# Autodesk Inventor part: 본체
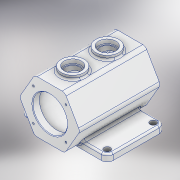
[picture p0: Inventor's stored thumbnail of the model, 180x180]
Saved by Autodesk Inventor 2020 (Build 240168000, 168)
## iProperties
Created: 2021-06
Part Number: 본체
Material: 알루미늄 6061
Document SubType Name: Modeling
Designer: 605-5
Mass: 1495.74 g
Surface Area: 1102.12 cm^2
Volume: 553.978 cm^3
Density: 2.7 g/cm^3
Appearance: 알루미늄 - 평지
Author: 605-5
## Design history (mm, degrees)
sketch "스케치1" dims "d0" = 105
  geometry: L1 (-26.25, 45.466)-(26.25, 45.466); L2 (26.25, 45.466)-(52.5, 0); L3 (52.5, 0)-(26.25, -45.466); L4 (26.25, -45.466)-(-26.25, -45.466); L5 (-26.25, -45.466)-(-52.5, 0); L6 (-52.5, 0)-(-26.25, 45.466); 3 further points
  constraints: 12 end point, 2 coincident, 1 horizontal alignment, 16 other
extrude "돌출1" new body sketch "스케치1" stored distance "d1" = 140; taper "d2" = 0 deg
node "작업 평면1"
sketch "스케치5"
  geometry: L1 (-75, -55)-(75, -55); L2 (75, -55)-(75, 45); L3 (75, 45)-(-75, 45); L4 (-75, 45)-(-75, -55); L5 (52.5, -70)-(26.25, -70) reference; L6 (26.25, 70)-(52.5, 70) reference; 3 further points
  constraints: 8 end point, 2 midpoint, 2 parallel, 1 horizontal, 1 perpendicular, 1 vertical alignment
  dimensions: "d27" = 150 distance between parallel lines of L2 L4; "d28" = 100 distance between parallel lines of L3 L1; "d103" = 25 distance between parallel lines of L3 L6
extrude "돌출4" join sketch "스케치5" distance "d29" = 12; taper "d30" = 0 deg
node "작업 평면2"
sketch "스케치6"
  geometry: L1 (-26.25, 70)-(26.25, 70) reference; C1 r 20 at (0, 30); C2 r 20 at (0, -30); 1 further point
  constraints: 2 centre point, 2 vertical alignment, 1 equal radius
  dimensions: "d32" = 40 diameter of C2; "d33" = 60 distance of C2.centre C1.centre; "d34" = 40 distance from line of C1.centre L1
extrude "돌출5" join sketch "스케치6" stored distance "d35" = 12; taper "d36" = 0 deg
fillet "모깎기2" dims "d37" = 10
sketch "스케치7"
  geometry: A1 r 10 centre (65, 45) between (75, 45) and (65, 55) reference; 2 further points
  constraints: 1 coincident
hole "구멍2" sketch "스케치7" at (65, 45) diameter "d38" = 11; stored, may be unused: countersink angle "d42" = 90 deg, drill point angle "d44" = 118 deg; dims "d39" = 6, "d40" = 4, "d41" = 2, "d43" = 8
sketch "스케치8"
  geometry: L1 (-30.561, 55)-(-65, 55) reference; L2 (-75, 45)-(-75, -35) reference; L3 (-65, -45)-(-30.561, -45) reference; 2 further points
  constraints: 1 other
  dimensions: "d52" = 14 distance from line of point (-61, 5) L2; "d104" = 50 distance from line of L3 point (-61, 5)
feature "엠보싱1" sketch "스케치8" dims "d32" = 40, "d33" = 60, "d34" = 40, "d53" = 0.5, "d54" = 0
sketch "스케치9"
  geometry: L1 (45.466, -70)-(0, -70) reference; L2 (0, 70)-(45.466, 70) reference; L3 (0, -70)-(0, 70) reference; L4 (0, -70)-(0, 70); L5 (30, -70)-(30, -58); L6 (30, -58)-(37.5, -58); L7 (37.5, -58)-(37.5, 58); L8 (37.5, 58)-(30, 58); L9 (30, 58)-(30, 70); 1 further point
  constraints: 12 end point, 3 perpendicular, 2 collinear, 2 point on line, 2 vertical, 1 horizontal
  dimensions: "d55" = 12 distance between parallel lines of L6 L1; "d56" = 75 diameter of L7 L3; "d57" = 60 diameter of L5 L3
revolve "회전1" sketch "스케치9" stored, may be unused: angle "d58" = 90 deg
sketch "스케치10"
  geometry: L1 (-28.284, 28.284)-(0, 0); L2 (0, 0)-(28.284, 28.284); L3 (0, 0)-(0, 40); C1 r 30 at (0, 0) reference; A1 r 40 centre (0, 0) between (-28.284, 28.284) and (28.284, 28.284); 2 further points
  constraints: 6 end point, 3 point on circle, 2 coincident, 1 centre point, 1 vertical
  dimensions: "d59" = 80 diameter of A1; "d60" = 45 deg angle of L3 L1; "d61" = 90 deg angle of L2 L1
hole "구멍3" sketch "스케치10" at (-28.284, 28.284) diameter "d62" = 3.242; stored, may be unused: countersink angle "d66" = 90 deg, drill point angle "d68" = 120 deg; dims "d63" = 8, "d64" = 4, "d65" = 2, "d67" = 10
sketch "스케치11" dims "d72" = 80
  geometry: 3 further points
  constraints: 2 vertical alignment, 1 coincident, 2 other
hole "구멍4" sketch "스케치11" at (0, 40) diameter "d73" = 3.242; stored, may be unused: countersink angle "d77" = 90 deg, drill point angle "d79" = 120 deg; dims "d74" = 8, "d75" = 4, "d76" = 2, "d78" = 10
sketch "스케치12"
  geometry: C1 r 20 at (0, 0) reference; C2 r 20 at (0, 60) reference; 3 further points
  constraints: 2 coincident
hole "구멍5" sketch "스케치12" at (0, 0), (0, 60) diameter "d83" = 25; stored, may be unused: countersink angle "d87" = 90 deg, drill point angle "d89" = 0 deg; dims "d84" = 8, "d85" = 30, "d86" = 8, "d88" = 36.75
fillet "모깎기3" dims "d90" = 5
chamfer "모따기1" distance "d91" = 1; stored, may be unused: second distance "d92" = 2, angle "d93" = 45 deg
fillet "모깎기4" dims "d94" = 8
fillet "모깎기5" dims "d95" = 3
fillet "모깎기9" dims "d99" = 8
fillet "모깎기10" dims "d100" = 3
fillet "모깎기11" dims "d101" = 3
sketch "스케치13"
  geometry: 1 further point
node "솔리드1"
pattern_linear "직사각형 패턴2" dims "d47" = 130, "d50" = 80
pattern_circular "원형 패턴1" dims angle "d70" = 360 deg
pattern_circular "원형 패턴2" dims angle "d81" = 360 deg
feature "A9D066F2-1C7D-4E18-AEED-F7BC21143FA4" dims "d38" = 11, "d39" = 6, "d40" = 4, "d41" = 2, "d42" = 90 deg, "d43" = 8, "d44" = 118 deg
other parameters: "d31" = 52.5
